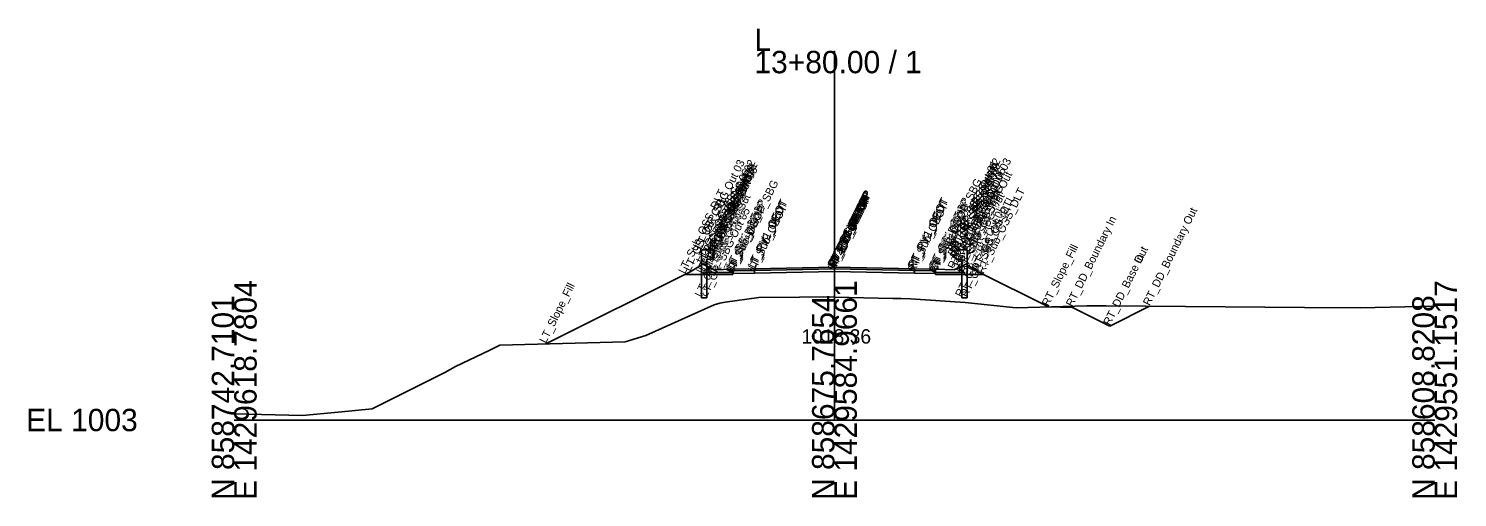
# Model space of a CAD drawing. Extents: x -26 to 2303, y -10 to 19558.
# Drawn here: x 1124.3 to 1302.8, y 12490.3 to 12549 of the extents above; entities that cross this region are included whole.
import ezdxf

# ---------------------------------------------------------------- set-up
doc = ezdxf.new("R2010")
doc.units = 0
for name, color, linetype in [('Default', 7, 'Continuous'), ('Exist Cross Section Cell', 7, 'Continuous'), ('Exist XS Center Line Elevation Label', 7, 'Continuous'), ('Exist XS Ground Line', 7, 'Continuous'), ('Prop CMT Conc Surface', 7, 'Continuous'), ('Prop CMT Concrete Structures', 7, 'Continuous'), ('Prop CMT Ditch DDE', 7, 'Continuous'), ('Prop CMT Guardrail SBG', 7, 'Continuous'), ('Prop CMT Pvmt Course 1', 7, 'Continuous'), ('Prop CMT Pvmt Course 2', 7, 'Continuous'), ('Prop CMT Pvmt Course SBG', 7, 'Continuous'), ('Prop CMT Pvmt Surface', 7, 'Continuous'), ('Prop CMT Pvmt Surface Shoulder', 7, 'Continuous'), ('Prop CMT Shld Paved Course 1', 7, 'Continuous'), ('Prop CMT Shld Paved Course 2', 7, 'Continuous'), ('Prop CMT Slope Grass', 7, 'Continuous'), ('Prop CMT Subgrade Earthwork', 7, 'Continuous'), ('Prop XS Dump Level', 7, 'Continuous')]:
    doc.layers.add(name, color=color, linetype=linetype)

msp = doc.modelspace()

# ---------------------------------------------------------------- linework, layer by layer
at = {"layer": 'Exist Cross Section Cell'}
for p, q in [((1225, 12500), (1225, 12546.19)), ((1150, 12500), (1225, 12500)), ((1225, 12500), (1300, 12500))]:
    msp.add_line(p, q, dxfattribs=at)
at = {"layer": 'Exist XS Ground Line'}
msp.add_lwpolyline([(1150, 12500.76), (1158.54, 12500.57), (1162.97, 12500.99), (1167.22, 12501.39), (1176.31, 12505.96), (1177.65, 12506.69), (1181.86, 12508.7), (1183.2, 12509.38), (1198.86, 12509.77), (1201.43, 12510.59), (1209.99, 12514.41), (1210.66, 12514.64), (1211.35, 12514.75), (1215.56, 12515.32), (1220.65, 12515.37), (1223.61, 12515.4), (1225, 12515.36), (1232.3, 12515.2), (1233.33, 12515.19), (1234.49, 12515.15), (1241.34, 12514.69), (1247.7, 12514.04), (1256.54, 12514.29), (1257.45, 12514.27), (1258.93, 12514.28), (1283.75, 12514.08), (1290.67, 12514.02), (1300, 12514.25)], dxfattribs=at)
at = {"layer": 'Prop CMT Conc Surface'}
for points in [[(1212.32, 12518.87), (1209.98, 12518.78), (1209.32, 12519.12)], [(1237.64, 12518.87), (1239.97, 12518.78), (1240.64, 12519.12)]]:
    msp.add_lwpolyline(points, dxfattribs=at)
at = {"layer": 'Prop CMT Concrete Structures'}
for points in [[(1212.32, 12518.87), (1209.98, 12518.78), (1209.32, 12519.12)], [(1209.32, 12519.12), (1209.32, 12518.46)], [(1212.32, 12518.46), (1212.32, 12518.87)], [(1237.64, 12518.87), (1239.97, 12518.78), (1240.64, 12519.12)], [(1237.64, 12518.46), (1237.64, 12518.87)], [(1240.64, 12519.12), (1240.64, 12518.46)], [(1209.32, 12518.46), (1212.32, 12518.46)], [(1240.64, 12518.46), (1237.64, 12518.46)]]:
    msp.add_lwpolyline(points, dxfattribs=at)
at = {"layer": 'Prop CMT Ditch DDE'}
for points in [[(1251.75, 12514.15), (1254.75, 12514.09), (1259.42, 12511.75)], [(1259.42, 12511.75), (1264.38, 12514.23)], [(1259.42, 12511.75), (1259.42, 12511.75)]]:
    msp.add_lwpolyline(points, dxfattribs=at)
at = {"layer": 'Prop CMT Guardrail SBG'}
for points in [[(1208.38, 12515.28), (1208.38, 12521.28)], [(1208.38, 12521.28), (1209.71, 12521.28), (1209.98, 12520.99)], [(1209.98, 12520.99), (1209.71, 12520.7)], [(1209.71, 12520.7), (1209.98, 12520.4)], [(1241.58, 12521.28), (1240.24, 12521.28), (1239.97, 12520.99)], [(1239.97, 12520.99), (1240.24, 12520.7)], [(1240.24, 12520.7), (1239.97, 12520.41)], [(1241.58, 12515.28), (1241.58, 12521.28)], [(1209.98, 12520.4), (1209.71, 12520.11), (1209.05, 12520.11)], [(1209.05, 12520.11), (1209.05, 12515.28)], [(1239.97, 12520.41), (1240.24, 12520.11), (1240.91, 12520.11)], [(1240.91, 12520.11), (1240.91, 12515.28)], [(1209.05, 12515.28), (1208.38, 12515.28)], [(1240.91, 12515.28), (1241.58, 12515.28)]]:
    msp.add_lwpolyline(points, dxfattribs=at)
at = {"layer": 'Prop CMT Pvmt Course 1'}
for points in [[(1225, 12519.13), (1215, 12518.93)], [(1215, 12518.93), (1215, 12518.72)], [(1215, 12518.72), (1225, 12518.92)], [(1225, 12518.92), (1225, 12519.13)], [(1225, 12519.13), (1235, 12518.93)], [(1225, 12518.92), (1225, 12519.13)], [(1235, 12518.72), (1225, 12518.92)], [(1235, 12518.93), (1235, 12518.72)]]:
    msp.add_lwpolyline(points, dxfattribs=at)
msp.add_lwpolyline([(1225, 12518.92), (1225, 12519), (1225, 12519), (1225, 12518.92)], close=True, dxfattribs=at)
msp.add_lwpolyline([(1225, 12518.92), (1225, 12519), (1225, 12519), (1225, 12518.92)], close=True, dxfattribs=at)
at = {"layer": 'Prop CMT Pvmt Course 2'}
for points in [[(1225, 12518.92), (1215, 12518.72)], [(1215, 12518.72), (1215, 12518.39)], [(1225, 12518.59), (1225, 12518.92)], [(1225, 12518.59), (1225, 12518.92)], [(1225, 12518.92), (1235, 12518.72)], [(1235, 12518.72), (1235, 12518.39)], [(1215, 12518.39), (1225, 12518.59)], [(1235, 12518.39), (1225, 12518.59)]]:
    msp.add_lwpolyline(points, dxfattribs=at)
at = {"layer": 'Prop CMT Pvmt Course SBG'}
for points in [[(1212.32, 12518.46), (1209.32, 12518.46), (1208.82, 12518.46), (1208.57, 12518.21)], [(1208.57, 12518.21), (1212.32, 12518.21)], [(1212.32, 12518.21), (1212.32, 12518.46)], [(1237.64, 12518.21), (1237.64, 12518.46)], [(1237.64, 12518.46), (1240.64, 12518.46), (1241.14, 12518.46), (1241.39, 12518.21)], [(1241.39, 12518.21), (1237.64, 12518.21)]]:
    msp.add_lwpolyline(points, dxfattribs=at)
at = {"layer": 'Prop CMT Pvmt Surface'}
for points in [[(1225, 12519.13), (1215, 12518.93)], [(1225, 12519.13), (1235, 12518.93)]]:
    msp.add_lwpolyline(points, dxfattribs=at)
at = {"layer": 'Prop CMT Pvmt Surface Shoulder'}
for points in [[(1215, 12518.93), (1212.32, 12518.87)], [(1235, 12518.93), (1237.64, 12518.87)]]:
    msp.add_lwpolyline(points, dxfattribs=at)
at = {"layer": 'Prop CMT Shld Paved Course 1'}
for points in [[(1215, 12518.93), (1212.32, 12518.87)], [(1212.32, 12518.87), (1212.32, 12518.66)], [(1212.32, 12518.66), (1215, 12518.72)], [(1215, 12518.72), (1215, 12518.93)], [(1235, 12518.93), (1237.64, 12518.87)], [(1235, 12518.72), (1235, 12518.93)], [(1237.64, 12518.67), (1235, 12518.72)], [(1237.64, 12518.87), (1237.64, 12518.67)]]:
    msp.add_lwpolyline(points, dxfattribs=at)
at = {"layer": 'Prop CMT Shld Paved Course 2'}
for points in [[(1215, 12518.72), (1212.32, 12518.66)], [(1215, 12518.39), (1215, 12518.72)], [(1235, 12518.72), (1237.64, 12518.67)], [(1235, 12518.39), (1235, 12518.72)], [(1212.32, 12518.66), (1212.32, 12518.46), (1212.32, 12518.33)], [(1212.32, 12518.33), (1215, 12518.39)], [(1237.64, 12518.33), (1235, 12518.39)], [(1237.64, 12518.67), (1237.64, 12518.46), (1237.64, 12518.33)]]:
    msp.add_lwpolyline(points, dxfattribs=at)
at = {"layer": 'Prop CMT Slope Grass'}
for points in [[(1209.32, 12519.12), (1208.55, 12519.52), (1206.98, 12518.54), (1188.95, 12509.52)], [(1240.64, 12519.12), (1241.41, 12519.52), (1242.97, 12518.54), (1251.75, 12514.15)]]:
    msp.add_lwpolyline(points, dxfattribs=at)
at = {"layer": 'Prop CMT Subgrade Earthwork'}
for points in [[(1212.32, 12518.21), (1208.57, 12518.21), (1206.32, 12518.21)], [(1215, 12518.39), (1212.32, 12518.33)], [(1212.32, 12518.33), (1212.32, 12518.21)], [(1225, 12518.59), (1215, 12518.39)], [(1225, 12518.59), (1235, 12518.39)], [(1235, 12518.39), (1237.64, 12518.33)], [(1237.64, 12518.33), (1237.64, 12518.21)], [(1237.64, 12518.21), (1241.39, 12518.21), (1243.64, 12518.21)]]:
    msp.add_lwpolyline(points, dxfattribs=at)

# ---------------------------------------------------------------- texts
at = {"layer": 'Default'}
msp.add_text('-', height=0.0001, dxfattribs=at).set_placement((1150, 12500))
at = {"layer": 'Exist Cross Section Cell'}
for s, p in [('L', (1215, 12546.19)), ('13+80.00 / 1', (1215, 12543.39)), ('EL 1003', (1124, 12498.6))]:
    msp.add_text(s, height=2.8, dxfattribs=at).set_placement(p)
for s, p in [('E 1429618.7804', (1152.8, 12490)), ('E 1429584.9661', (1227.8, 12490)), ('E 1429551.1517', (1302.8, 12490)), ('N 858742.7101', (1150, 12490)), ('N 858675.7654', (1225, 12490)), ('N 858608.8208', (1300, 12490))]:
    msp.add_text(s, height=2.8, rotation=90, dxfattribs=at).set_placement(p)
at = {"layer": 'Exist XS Center Line Elevation Label'}
msp.add_text('1018.36', height=1.8, dxfattribs=at).set_placement((1220.88, 12509.56))
at = {"layer": 'Prop XS Dump Level'}
for s, p in [('LT_GR_SBG Out 03', (1208.38, 12521.28)), ('LT_GR_SBG Out 06', (1209.05, 12520.11)), ('LT_GR_SBG Out 02', (1209.71, 12521.28)), ('LT_GR_SBG Out 09', (1209.71, 12520.7)), ('LT_GR_SBG Out 07', (1209.71, 12520.11)), ('LT_GR_SBG Out 01', (1209.98, 12520.99)), ('LT_GR_SBG Out 08', (1209.98, 12520.4)), ('RT_GR_SBG Out 01', (1239.97, 12520.99)), ('RT_GR_SBG Out 08', (1239.97, 12520.41)), ('RT_GR_SBG Out 02', (1240.24, 12521.28)), ('RT_GR_SBG Out 09', (1240.24, 12520.7)), ('RT_GR_SBG Out 07', (1240.24, 12520.11)), ('RT_GR_SBG Out 06', (1240.91, 12520.11)), ('RT_GR_SBG Out 03', (1241.58, 12521.28)), ('LT_SBG_C1 Shelf Out', (1208.82, 12518.46)), ('LT_Sub_OEOP_SBG', (1212.32, 12518.21)), ('RT_Sub_OEOP_SBG', (1237.64, 12518.21)), ('RT_CG_Top_BOC', (1240.64, 12519.12)), ('RT_SBG_C1 Shelf Out', (1241.14, 12518.46)), ('LT_Sub_OSS_DLT', (1206.32, 12518.21)), ('LT_GS_OS_CTL', (1206.98, 12518.54)), ('LT_GS_OS_SBG', (1208.55, 12519.52)), ('LT_Sub_SBG Out', (1208.57, 12518.21)), ('LT_CG_Top_BOC', (1209.32, 12519.12)), ('LT_CG_Bot_BOC', (1209.32, 12518.46)), ('LT_CG_Top_Gut', (1209.98, 12518.78)), ('LT_PS1_OEOP', (1212.32, 12518.87)), ('LT_PV1_OEOT', (1215, 12518.93)), ('RT_PV1_OEEOP', (1225, 12519)), ('RT_PV2_OEEOP', (1225, 12518.92)), ('LT_PV1_OEEOP', (1225, 12519)), ('LT_PV2_OEEOP', (1225, 12518.92)), ('RT_Sub_OEEOP', (1225, 12518.59)), ('RT_PV1_IEEOP', (1225, 12519)), ('RT_PV2_IEEOP', (1225, 12518.92)), ('LT_Sub_OEEOP', (1225, 12518.59)), ('LT_PV1_IEEOP', (1225, 12519)), ('LT_PV2_IEEOP', (1225, 12518.92)), ('RT_PV1_OEOT', (1235, 12518.93)), ('RT_PV2_OEOT', (1235, 12518.72)), ('RT_PS1_OEOP', (1237.64, 12518.87)), ('RT_CG_Top_Gut', (1239.97, 12518.78)), ('RT_CG_Bot_BOC', (1240.64, 12518.46)), ('RT_Sub_SBG Out', (1241.39, 12518.21)), ('RT_GS_OS_SBG', (1241.41, 12519.52)), ('RT_GS_OS_CTL', (1242.97, 12518.54)), ('RT_Sub_OSS_DLT', (1243.64, 12518.21)), ('LT_GR_SBG Out 04', (1208.38, 12515.28)), ('LT_GR_SBG Out 05', (1209.05, 12515.28)), ('LT_PS2_OEOP', (1212.32, 12518.66)), ('LT_Sub_OEOP', (1212.32, 12518.33)), ('LT_CG_Bot_IE', (1212.32, 12518.46)), ('LT_PV2_OEOT', (1215, 12518.72)), ('LT_Sub_OEOT', (1215, 12518.39)), ('RT_Sub_OEOT', (1235, 12518.39)), ('RT_PS2_OEOP', (1237.64, 12518.67)), ('RT_Sub_OEOP', (1237.64, 12518.33)), ('RT_CG_Bot_IE', (1237.64, 12518.46)), ('RT_GR_SBG Out 05', (1240.91, 12515.28)), ('RT_GR_SBG Out 04', (1241.58, 12515.28)), ('RT_DD_Boundary Out', (1264.38, 12514.23)), ('PV1_PGL', (1225, 12519.13)), ('PV2_PGL', (1225, 12518.92)), ('RT_DD_Boundary In', (1254.75, 12514.09)), ('RT_Slope_Fill', (1251.75, 12514.15)), ('RT_DD_Base Out', (1259.42, 12511.75)), ('RT_DD_Base In', (1259.42, 12511.75)), ('LT_Slope_Fill', (1188.95, 12509.52))]:
    msp.add_text(s, height=1, rotation=63.5833, dxfattribs=at).set_placement(p)

doc.saveas('drawing.dxf')
